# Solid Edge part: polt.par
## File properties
Title: polt
Author: Stella-Marii
Template: iso metric part.par
Last saved by: Stella-Marii
Revision: 6
Application: Solid Edge
Document Number: 31
Density: 7833,000 kg/m^3
Accuracy: 0,990
Username: Stella-Marii
Material: Steel, structural
Face Style: Steel
Fill Style: ANSI32(Steel)
Virtual Style: Brushed steel
Grouping: Metals\Steel
LibraryName: Materials
Coef. of Thermal Exp: 1.3e-05
Thermal Conductivity: 32.0
Specific Heat: 481.0
Modulus of Elasticity: 199947953000.0
Poisson's Ratio: 0.29
Yield Stress: 262000766.0
Ultimate Stress: 358527364.0
Elongation: 0.0
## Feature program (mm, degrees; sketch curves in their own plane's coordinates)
sketch for "unnamed Protrusion 1" plane through (0, 0, 0) normal (0, 0, 1) x-axis (1, 0, 0)
  circle centre (0, 0) radius 5
extrude "unnamed Protrusion 1" add finite 55 along +normal
helix cutout "HelixCutout_3"  Pitch = 2 mm; NumberOfTurns = 40
sketch for "unnamed RevolvedProtrusion 1" plane through (0, 0, 0) normal (0, -1, 0) x-axis (1, 0, 0)
  arc centre (0, 55.5534) radius 6.8028 from (6.8028, 55.5534) to (0, 62.3562) ccw
  line (6.8028, 55) -> (6.8028, 55.5534)
  line (0, 55) -> (6.8028, 55)
  dimension (linear) = 6.8028
revolve "unnamed RevolvedProtrusion 1" add full turn 360 deg about sketch line (0, 55) -> (0, 62.3562)
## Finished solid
Body 1: solid body, 9 faces, 15 edges, 8 vertices.
  Faces by surface: cylinder 3, plane 3, spline 2, sphere 1
  Edges by curve: circle 5, line 4, spline 4, intersection 2
Bounding box of the edges (mm; curved faces can reach further): 13.606 x 13.606 x 55.553, from (-6.8028, -6.8028, 0) to (6.8028, 6.8028, 55.5534).
Cylindrical faces by radius (mm): R4 x1, R5 x1, R6.8028 x1
Spherical faces by radius (mm): R6.8028 x1
Planar faces by outward normal: +y 1, -z 2
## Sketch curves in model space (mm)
line (0, 0, 0) -> (0, 0, 4.1871)
line (5.738, 0, 1) -> (5.738, 0, 2)
line (5.738, 0, 2) -> (4, 0, 2)
line (4, 0, 2) -> (4, 0, 1)
line (4, 0, 1) -> (5.738, 0, 1)
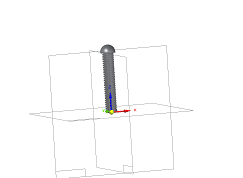
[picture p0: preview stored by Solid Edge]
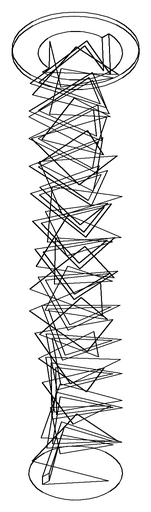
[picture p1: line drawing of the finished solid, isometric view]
